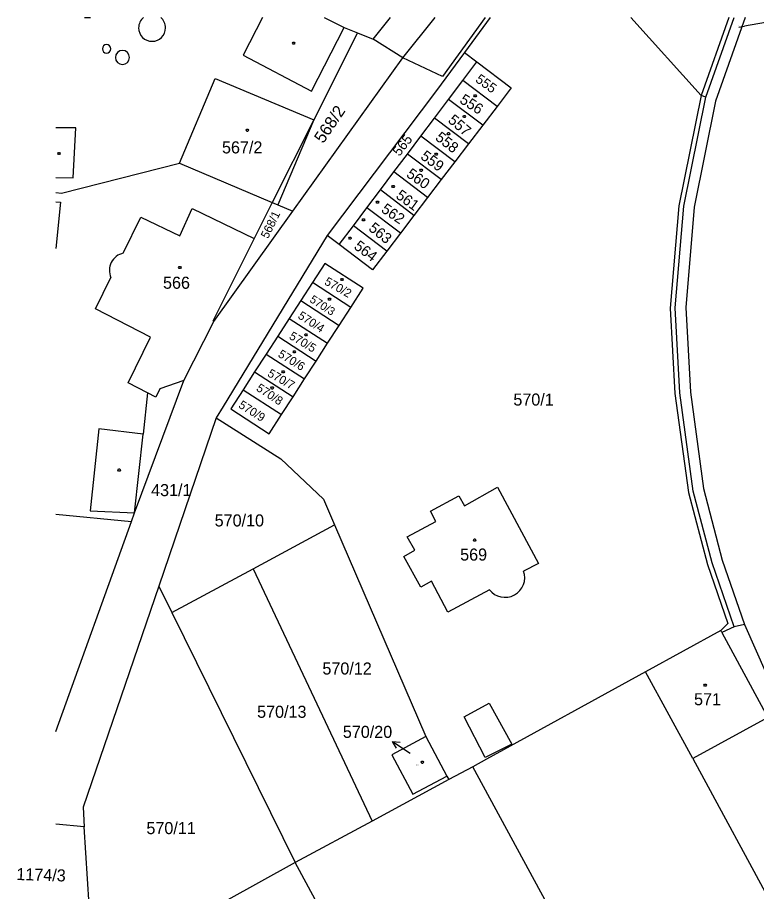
# Model space of a CAD drawing. Extents: x -621797 to -620972, y -1175539 to -1174697.
# Drawn here: x -621795.7 to -621691.5, y -1174822.1 to -1174699 of the extents above; entities that cross this region are included whole.
import ezdxf

# ---------------------------------------------------------------- set-up
doc = ezdxf.new("R2010")
doc.units = 0
for name, color, linetype in [('INZ mimo EON - nadz', 7, 'Continuous'), ('Rozvod plynu EON', 7, 'Continuous'), ('SDEL EON - popis', 7, 'Continuous'), ('Silnoproud EON', 7, 'Continuous'), ('Silnoproud EON - popis', 7, 'Continuous')]:
    doc.layers.add(name, color=color, linetype=linetype)

msp = doc.modelspace()

# ---------------------------------------------------------------- linework, layer by layer
at = {"layer": 'INZ mimo EON - nadz'}
for p, q in [((-621694.04, -1174700.34), (-621693.24, -1174700.2)), ((-621690.286, -1174699.679), (-621693.24, -1174700.2)), ((-621742.866, -1174800.956), (-621740.35, -1174802.59))]:
    msp.add_line(p, q, dxfattribs=at)
msp.add_lwpolyline([(-621742.3, -1174801.92), (-621742.866, -1174800.956), (-621741.755, -1174801.082)], dxfattribs=at)
at = {"layer": 'Rozvod plynu EON'}
for points in [[(-621756.68, -1174702.44), (-621756.59, -1174702.59), (-621756.68, -1174702.74), (-621756.86, -1174702.74), (-621756.95, -1174702.59), (-621756.86, -1174702.44)], [(-621731.12, -1174709.86), (-621731.03, -1174710.01), (-621731.12, -1174710.16), (-621731.3, -1174710.16), (-621731.39, -1174710.01), (-621731.3, -1174709.86)], [(-621732.64, -1174712.75), (-621732.55, -1174712.9), (-621732.64, -1174713.05), (-621732.82, -1174713.05), (-621732.91, -1174712.9), (-621732.82, -1174712.75)], [(-621763.21, -1174714.71), (-621763.12, -1174714.86), (-621763.21, -1174715.01), (-621763.39, -1174715.01), (-621763.48, -1174714.86), (-621763.39, -1174714.71)], [(-621734.85, -1174715.18), (-621734.76, -1174715.33), (-621734.85, -1174715.48), (-621735.03, -1174715.48), (-621735.12, -1174715.33), (-621735.03, -1174715.18)], [(-621789.75, -1174717.96), (-621789.66, -1174718.11), (-621789.75, -1174718.26), (-621789.93, -1174718.26), (-621790.02, -1174718.11), (-621789.93, -1174717.96)], [(-621736.59, -1174718.06), (-621736.5, -1174718.21), (-621736.59, -1174718.36), (-621736.77, -1174718.36), (-621736.86, -1174718.21), (-621736.77, -1174718.06)], [(-621738.72, -1174720.34), (-621738.63, -1174720.49), (-621738.72, -1174720.64), (-621738.9, -1174720.64), (-621738.99, -1174720.49), (-621738.9, -1174720.34)], [(-621742.65, -1174722.61), (-621742.56, -1174722.76), (-621742.65, -1174722.91), (-621742.83, -1174722.91), (-621742.92, -1174722.76), (-621742.83, -1174722.61)], [(-621744.87, -1174724.82), (-621744.78, -1174724.97), (-621744.87, -1174725.12), (-621745.05, -1174725.12), (-621745.14, -1174724.97), (-621745.05, -1174724.82)], [(-621746.84, -1174727.33), (-621746.75, -1174727.48), (-621746.84, -1174727.63), (-621747.02, -1174727.63), (-621747.11, -1174727.48), (-621747.02, -1174727.33)], [(-621748.74, -1174729.91), (-621748.65, -1174730.06), (-621748.74, -1174730.21), (-621748.92, -1174730.21), (-621749.01, -1174730.06), (-621748.92, -1174729.91)], [(-621772.73, -1174734.04), (-621772.64, -1174734.19), (-621772.73, -1174734.34), (-621772.91, -1174734.34), (-621773, -1174734.19), (-621772.91, -1174734.04)], [(-621749.87, -1174735.74), (-621749.78, -1174735.89), (-621749.87, -1174736.04), (-621750.05, -1174736.04), (-621750.14, -1174735.89), (-621750.05, -1174735.74)], [(-621751.63, -1174738.5), (-621751.54, -1174738.65), (-621751.63, -1174738.8), (-621751.81, -1174738.8), (-621751.9, -1174738.65), (-621751.81, -1174738.5)], [(-621754.95, -1174743.53), (-621754.86, -1174743.68), (-621754.95, -1174743.83), (-621755.13, -1174743.83), (-621755.22, -1174743.68), (-621755.13, -1174743.53)], [(-621756.59, -1174745.93), (-621756.5, -1174746.08), (-621756.59, -1174746.23), (-621756.77, -1174746.23), (-621756.86, -1174746.08), (-621756.77, -1174745.93)], [(-621758.15, -1174748.74), (-621758.06, -1174748.89), (-621758.15, -1174749.04), (-621758.33, -1174749.04), (-621758.42, -1174748.89), (-621758.33, -1174748.74)], [(-621759.71, -1174751.01), (-621759.62, -1174751.16), (-621759.71, -1174751.31), (-621759.89, -1174751.31), (-621759.98, -1174751.16), (-621759.89, -1174751.01)], [(-621781.26, -1174762.57), (-621781.17, -1174762.72), (-621781.26, -1174762.87), (-621781.44, -1174762.87), (-621781.53, -1174762.72), (-621781.44, -1174762.57)], [(-621731.18, -1174772.43), (-621731.09, -1174772.58), (-621731.18, -1174772.73), (-621731.36, -1174772.73), (-621731.45, -1174772.58), (-621731.36, -1174772.43)], [(-621698.69, -1174792.89), (-621698.6, -1174793.04), (-621698.69, -1174793.19), (-621698.87, -1174793.19), (-621698.96, -1174793.04), (-621698.87, -1174792.89)], [(-621738.55, -1174803.75), (-621738.46, -1174803.9), (-621738.55, -1174804.05), (-621738.73, -1174804.05), (-621738.82, -1174803.9), (-621738.73, -1174803.75)]]:
    msp.add_lwpolyline(points, close=True, dxfattribs=at)
at = {"layer": 'SDEL EON - popis'}
for p, q in [((-621761.154, -1174698.96), (-621763.88, -1174704.29)), ((-621741.38, -1174704.64), (-621736.844, -1174698.96)), ((-621695.456, -1174698.96), (-621699.33, -1174709.94)), ((-621754.28, -1174709.34), (-621749.67, -1174700.36)), ((-621763.88, -1174704.29), (-621754.28, -1174709.34)), ((-621772.87, -1174719.5), (-621767.82, -1174707.58)), ((-621767.82, -1174707.58), (-621753.93, -1174713.37)), ((-621699.33, -1174709.94), (-621702.51, -1174725.48)), ((-621753.93, -1174713.37), (-621759, -1174725.37)), ((-621787.49, -1174714.53), (-621790.31, -1174714.488)), ((-621787.85, -1174721.55), (-621787.49, -1174714.53)), ((-621790.31, -1174721.507), (-621787.85, -1174721.55)), ((-621790.31, -1174724.914), (-621789.63, -1174724.98)), ((-621789.63, -1174724.98), (-621790.31, -1174731.528)), ((-621702.51, -1174725.48), (-621703.7, -1174739.92)), ((-621703.7, -1174739.92), (-621703.07, -1174751.95)), ((-621777.35, -1174751.86), (-621777.98, -1174757.66)), ((-621703.07, -1174751.95), (-621701.13, -1174765.89)), ((-621784.25, -1174756.93), (-621785.47, -1174768.46)), ((-621777.98, -1174757.66), (-621784.25, -1174756.93)), ((-621779.19, -1174768.73), (-621777.98, -1174757.66)), ((-621701.13, -1174765.89), (-621698.48, -1174776.03)), ((-621785.47, -1174768.46), (-621779.19, -1174768.73)), ((-621698.48, -1174776.03), (-621695.57, -1174784.36)), ((-621695.57, -1174784.36), (-621696.6, -1174785.35)), ((-621732.75, -1174797.49), (-621729.23, -1174795.58)), ((-621729.23, -1174795.58), (-621726.05, -1174801.36)), ((-621729.77, -1174803.23), (-621732.75, -1174797.49)), ((-621726.05, -1174801.36), (-621729.77, -1174803.23)), ((-621700.54, -1174803.38), (-621664.27, -1174870.06)), ((-621713.24, -1174897.34), (-621756.56, -1174818.04))]:
    msp.add_line(p, q, dxfattribs=at)
for centre, radius, start, end in [((-621785.83, -1174694.28), 4.7, 264.71241, 275.28759), ((-621776.72, -1174700.42), 1.9, 129.78769, 180), ((-621776.72, -1174700.42), 1.9, 0, 50.21231), ((-621776.72, -1174700.42), 1.9, 180, 0), ((-621783.13, -1174703.38), 0.6, 90, 270), ((-621783.13, -1174703.38), 0.6, 270, 90), ((-621780.9, -1174704.59), 1, 0, 180), ((-621780.9, -1174704.59), 1, 180, 0)]:
    msp.add_arc(centre, radius, start, end, dxfattribs=at)
at = {"layer": 'Silnoproud EON'}
for p, q in [((-621752.461, -1174698.96), (-621749.67, -1174700.36)), ((-621745.56, -1174702.01), (-621743.129, -1174698.96)), ((-621729.795, -1174698.96), (-621735.81, -1174707.26)), ((-621729.101, -1174698.96), (-621732.71, -1174703.89)), ((-621699.33, -1174709.94), (-621709.259, -1174698.96)), ((-621698.68, -1174710.19), (-621694.714, -1174698.96)), ((-621693.149, -1174698.96), (-621697.33, -1174710.73)), ((-621749.67, -1174700.36), (-621747.77, -1174701.13)), ((-621747.77, -1174701.13), (-621753.93, -1174713.37)), ((-621747.77, -1174701.13), (-621745.56, -1174702.01)), ((-621741.38, -1174704.64), (-621745.56, -1174702.01)), ((-621732.71, -1174703.89), (-621736.63, -1174709.23)), ((-621732.71, -1174703.89), (-621730.96, -1174705.21)), ((-621756.88, -1174726.26), (-621741.38, -1174704.64)), ((-621735.81, -1174707.26), (-621741.38, -1174704.64)), ((-621732.95, -1174707.86), (-621730.96, -1174705.21)), ((-621730.96, -1174705.21), (-621726.11, -1174708.85)), ((-621734.94, -1174710.5), (-621732.95, -1174707.86)), ((-621728.12, -1174711.49), (-621732.95, -1174707.86)), ((-621736.63, -1174709.23), (-621752.06, -1174729.7)), ((-621726.11, -1174708.85), (-621728.12, -1174711.49)), ((-621736.94, -1174713.15), (-621734.94, -1174710.5)), ((-621730.13, -1174714.13), (-621734.94, -1174710.5)), ((-621701.81, -1174725.54), (-621698.68, -1174710.19)), ((-621698.68, -1174710.19), (-621699.33, -1174709.94)), ((-621728.12, -1174711.49), (-621730.13, -1174714.13)), ((-621697.33, -1174710.73), (-621700.35, -1174725.68)), ((-621753.93, -1174713.37), (-621759.8, -1174725.03)), ((-621738.84, -1174715.67), (-621736.94, -1174713.15)), ((-621732.14, -1174716.77), (-621736.94, -1174713.15)), ((-621730.13, -1174714.13), (-621732.14, -1174716.77)), ((-621740.75, -1174718.2), (-621738.84, -1174715.67)), ((-621734.06, -1174719.29), (-621738.84, -1174715.67)), ((-621732.14, -1174716.77), (-621734.06, -1174719.29)), ((-621742.65, -1174720.72), (-621740.75, -1174718.2)), ((-621735.98, -1174721.81), (-621740.75, -1174718.2)), ((-621789.5, -1174723.69), (-621772.87, -1174719.5)), ((-621772.87, -1174719.5), (-621759.8, -1174725.03)), ((-621734.06, -1174719.29), (-621735.98, -1174721.81)), ((-621744.55, -1174723.25), (-621742.65, -1174720.72)), ((-621737.9, -1174724.32), (-621742.65, -1174720.72)), ((-621735.98, -1174721.81), (-621737.9, -1174724.32)), ((-621790.31, -1174723.611), (-621789.5, -1174723.69)), ((-621746.46, -1174725.78), (-621744.55, -1174723.25)), ((-621739.82, -1174726.84), (-621744.55, -1174723.25)), ((-621759.8, -1174725.03), (-621762.35, -1174730.1)), ((-621759.8, -1174725.03), (-621759, -1174725.37)), ((-621759, -1174725.37), (-621756.88, -1174726.26)), ((-621737.9, -1174724.32), (-621739.82, -1174726.84)), ((-621772.83, -1174729.72), (-621771.09, -1174725.88)), ((-621771.09, -1174725.88), (-621762.35, -1174730.1)), ((-621768.03, -1174741.81), (-621756.88, -1174726.26)), ((-621748.36, -1174728.3), (-621746.46, -1174725.78)), ((-621741.74, -1174729.36), (-621746.46, -1174725.78)), ((-621703, -1174739.89), (-621701.81, -1174725.54)), ((-621700.35, -1174725.68), (-621701.5, -1174739.81)), ((-621780.78, -1174732.17), (-621778.29, -1174727.1)), ((-621778.29, -1174727.1), (-621772.83, -1174729.72)), ((-621739.82, -1174726.84), (-621741.74, -1174729.36)), ((-621750.36, -1174730.95), (-621748.36, -1174728.3)), ((-621743.66, -1174731.88), (-621748.36, -1174728.3)), ((-621762.35, -1174730.1), (-621768.15, -1174741.75)), ((-621752.06, -1174729.7), (-621766.69, -1174753.75)), ((-621750.36, -1174730.95), (-621752.06, -1174729.7)), ((-621741.74, -1174729.36), (-621743.66, -1174731.88)), ((-621745.67, -1174734.52), (-621750.36, -1174730.95)), ((-621743.66, -1174731.88), (-621745.67, -1174734.52)), ((-621752.38, -1174733.6), (-621754.14, -1174736.32)), ((-621746.98, -1174737.09), (-621752.38, -1174733.6)), ((-621784.7, -1174740.02), (-621782.52, -1174735.6)), ((-621754.14, -1174736.32), (-621755.77, -1174738.84)), ((-621748.73, -1174739.82), (-621754.14, -1174736.32)), ((-621748.73, -1174739.82), (-621746.98, -1174737.09)), ((-621755.77, -1174738.84), (-621757.4, -1174741.36)), ((-621755.77, -1174738.84), (-621750.36, -1174742.34)), ((-621776.96, -1174743.98), (-621784.7, -1174740.02)), ((-621750.36, -1174742.34), (-621748.73, -1174739.82)), ((-621702.37, -1174751.85), (-621703, -1174739.89)), ((-621701.5, -1174739.81), (-621700.87, -1174751.77)), ((-621757.4, -1174741.36), (-621759.02, -1174743.87)), ((-621757.4, -1174741.36), (-621751.99, -1174744.85)), ((-621772.26, -1174750.13), (-621768.03, -1174741.81)), ((-621768.15, -1174741.75), (-621768.03, -1174741.81)), ((-621751.99, -1174744.85), (-621750.36, -1174742.34)), ((-621780.08, -1174750.45), (-621776.96, -1174743.98)), ((-621759.02, -1174743.87), (-621760.65, -1174746.39)), ((-621759.02, -1174743.87), (-621753.62, -1174747.37)), ((-621753.62, -1174747.37), (-621751.99, -1174744.85)), ((-621760.65, -1174746.39), (-621762.28, -1174748.9)), ((-621760.65, -1174746.39), (-621755.24, -1174749.88)), ((-621755.24, -1174749.88), (-621753.62, -1174747.37)), ((-621762.28, -1174748.9), (-621763.9, -1174751.42)), ((-621762.28, -1174748.9), (-621756.86, -1174752.4)), ((-621756.86, -1174752.4), (-621755.24, -1174749.88)), ((-621777.35, -1174751.86), (-621780.08, -1174750.45)), ((-621779.19, -1174768.73), (-621772.26, -1174750.13)), ((-621772.26, -1174750.13), (-621775.62, -1174751.29)), ((-621776.21, -1174752.44), (-621777.35, -1174751.86)), ((-621775.62, -1174751.29), (-621776.21, -1174752.44)), ((-621763.9, -1174751.42), (-621765.64, -1174754.1)), ((-621763.9, -1174751.42), (-621758.5, -1174754.92)), ((-621758.5, -1174754.92), (-621756.86, -1174752.4)), ((-621700.46, -1174765.71), (-621702.37, -1174751.85)), ((-621700.87, -1174751.77), (-621699.01, -1174765.33)), ((-621766.69, -1174753.75), (-621767.68, -1174755.38)), ((-621765.64, -1174754.1), (-621760.24, -1174757.63)), ((-621760.24, -1174757.63), (-621758.5, -1174754.92)), ((-621767.68, -1174755.38), (-621775.79, -1174779.07)), ((-621767.68, -1174755.38), (-621758.56, -1174761.16)), ((-621758.56, -1174761.16), (-621752.59, -1174766.84)), ((-621732.69, -1174767.77), (-621728.05, -1174765.13)), ((-621728.05, -1174765.13), (-621724.66, -1174771.45)), ((-621697.82, -1174775.8), (-621700.46, -1174765.71)), ((-621699.01, -1174765.33), (-621696.37, -1174775.42)), ((-621752.59, -1174766.84), (-621751.03, -1174770.46)), ((-621737.51, -1174768.54), (-621733.48, -1174766.37)), ((-621733.48, -1174766.37), (-621732.69, -1174767.77)), ((-621790.31, -1174768.918), (-621779.64, -1174769.97)), ((-621779.64, -1174769.97), (-621779.19, -1174768.73)), ((-621736.75, -1174769.95), (-621737.51, -1174768.54)), ((-621790.31, -1174799.568), (-621779.64, -1174769.97)), ((-621762.5, -1174776.62), (-621751.03, -1174770.46)), ((-621751.03, -1174770.46), (-621738.17, -1174800.27)), ((-621740.76, -1174772.12), (-621736.75, -1174769.95)), ((-621739.7, -1174774.03), (-621740.76, -1174772.12)), ((-621724.66, -1174771.45), (-621722.29, -1174775.88)), ((-621741.25, -1174774.89), (-621739.7, -1174774.03)), ((-621738.87, -1174779.22), (-621741.25, -1174774.89)), ((-621694.68, -1174784.79), (-621697.82, -1174775.8)), ((-621696.37, -1174775.42), (-621693.26, -1174784.48)), ((-621773.96, -1174782.78), (-621762.5, -1174776.62)), ((-621762.5, -1174776.62), (-621745.72, -1174812.19)), ((-621722.29, -1174775.88), (-621724.37, -1174776.95)), ((-621775.79, -1174779.07), (-621786.46, -1174810.24)), ((-621775.79, -1174779.07), (-621773.96, -1174782.78)), ((-621737.37, -1174778.39), (-621738.87, -1174779.22)), ((-621735.03, -1174782.76), (-621737.37, -1174778.39)), ((-621729.2, -1174779.58), (-621735.03, -1174782.76)), ((-621773.96, -1174782.78), (-621756.56, -1174818.04)), ((-621693.26, -1174784.48), (-621694.68, -1174784.79)), ((-621693.26, -1174784.48), (-621687.47, -1174797.58)), ((-621696.6, -1174785.35), (-621707.2, -1174791.13)), ((-621696.45, -1174785.61), (-621696.6, -1174785.35)), ((-621694.68, -1174784.79), (-621696.45, -1174785.61)), ((-621696.45, -1174785.61), (-621689.95, -1174797.61)), ((-621707.2, -1174791.13), (-621729.59, -1174803.48)), ((-621700.54, -1174803.38), (-621707.2, -1174791.13)), ((-621689.95, -1174797.61), (-621700.54, -1174803.38)), ((-621738.17, -1174800.27), (-621742.96, -1174802.86)), ((-621738.17, -1174800.27), (-621735.17, -1174805.83)), ((-621742.96, -1174802.86), (-621739.99, -1174808.41)), ((-621729.59, -1174803.48), (-621731.51, -1174804.52)), ((-621731.51, -1174804.52), (-621734.89, -1174806.34)), ((-621690, -1174880.99), (-621731.51, -1174804.52)), ((-621734.89, -1174806.34), (-621745.72, -1174812.19)), ((-621739.99, -1174808.41), (-621735.17, -1174805.83)), ((-621735.17, -1174805.83), (-621734.89, -1174806.34)), ((-621786.46, -1174810.24), (-621786.28, -1174812.99)), ((-621786.28, -1174812.99), (-621790.31, -1174812.602)), ((-621745.72, -1174812.19), (-621756.56, -1174818.04)), ((-621785.57, -1174823.97), (-621786.28, -1174812.99)), ((-621756.56, -1174818.04), (-621766.48, -1174823.5))]:
    msp.add_line(p, q, dxfattribs=at)
for centre, radius, start, end in [((-621780.287, -1174734.577), 2.457, 101.58204, 204.62164), ((-621727, -1174777.87), 2.786, 217.85157, 19.2862)]:
    msp.add_arc(centre, radius, start, end, dxfattribs=at)

# ---------------------------------------------------------------- texts
at = {"layer": 'INZ mimo EON - nadz'}
msp.add_text('570/20', height=1.7, dxfattribs=at).set_placement((-621749.843, -1174800.46))
at = {"layer": 'Silnoproud EON - popis'}
for s, height, rotation, p in [('433', 0.1, 66.57769, (-621694.034, -1174700.327)), ('555', 1.36, 324.52329, (-621731.265, -1174707.937)), ('556', 1.5, 327.61727, (-621733.503, -1174710.902)), ('568/2', 1.7, 55.80609, (-621752.607, -1174716.814)), ('557', 1.5, 319.48127, (-621735.131, -1174713.616)), ('565', 1.4, 52.19646, (-621741.86, -1174718.606)), ('558', 1.5, 322.17417, (-621736.925, -1174716.108)), ('559', 1.5, 324.00763, (-621739.011, -1174718.783)), ('560', 1.5, 324.92437, (-621741.009, -1174721.31)), ('561', 1.5, 324.00763, (-621742.491, -1174724.313)), ('562', 1.5, 325.7838, (-621744.557, -1174726.278)), ('568/1', 1.2, 63.88479, (-621760.396, -1174730.21)), ('563', 1.5, 321.31473, (-621746.326, -1174728.861)), ('564', 1.5, 323.0909, (-621748.393, -1174731.446)), ('570/2', 1.2, 330.31017, (-621752.544, -1174736.503)), ('570/3', 1.14, 327.33079, (-621754.616, -1174738.964)), ('570/4', 1.19, 327.04431, (-621756.276, -1174741.26)), ('570/5', 1.2, 329.39344, (-621757.516, -1174744.165)), ('570/6', 1.2, 328.4767, (-621759.087, -1174746.698)), ('570/7', 1.2, 330.31017, (-621760.554, -1174749.443)), ('570/8', 1.2, 326.70054, (-621762.15, -1174751.452)), ('570/9', 1.19, 327.61727, (-621764.639, -1174753.84)), ('1174/3', 1.7, 358.21321, (-621795.867, -1174820.482))]:
    msp.add_text(s, height=height, rotation=rotation, dxfattribs=at).set_placement(p)
for s, height, p in [('567/2', 1.7, (-621766.873, -1174718.11)), ('566', 1.7, (-621775.183, -1174737.18)), ('570/1', 1.7, (-621725.813, -1174753.64)), ('431/1', 1.7, (-621776.863, -1174766.4)), ('570/10', 1.7, (-621767.903, -1174770.67)), ('569', 1.7, (-621733.313, -1174775.48)), ('570/12', 1.7, (-621752.723, -1174791.53)), ('571', 1.7, (-621700.353, -1174795.86)), ('570/13', 1.7, (-621761.923, -1174797.63)), ('570/20', 0.1, (-621739.636, -1174804.33)), ('570/11', 1.7, (-621777.523, -1174814.02))]:
    msp.add_text(s, height=height, dxfattribs=at).set_placement(p)

doc.saveas('drawing.dxf')
